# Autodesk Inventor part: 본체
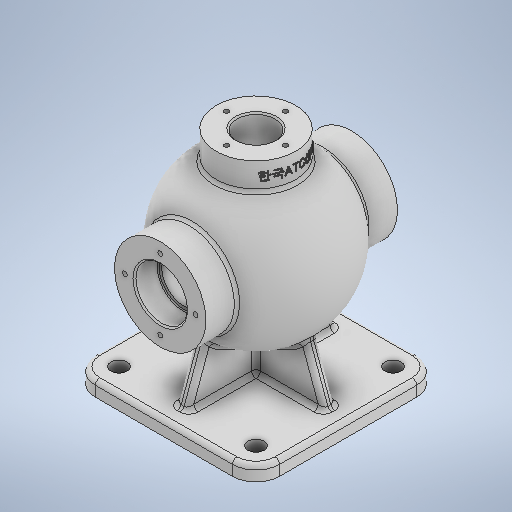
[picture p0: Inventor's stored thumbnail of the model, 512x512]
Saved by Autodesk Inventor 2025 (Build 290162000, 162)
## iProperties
Created: 2024-07
Part Number: 본체
Material: 일반
Document SubType Name: Modeling
Designer: onair
Density: 1 g/cm^3
Appearance: 기본값
Mass: 565.455 g
Surface Area: 1173.81 cm^2
Volume: 565.455 cm^3
Author: onair
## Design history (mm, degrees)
sketch "스케치1"
  geometry: L1 (46.5, -62.5)-(-46.5, -62.5); L2 (-62.5, -46.5)-(-62.5, 46.5); L3 (-46.5, 62.5)-(46.5, 62.5); L4 (62.5, 46.5)-(62.5, -46.5); L5 (62.5, -62.5)-(-62.5, 62.5); L6 (-62.5, -62.5)-(62.5, 62.5); A1 r 16 centre (-46.5, 46.5) between (-46.5, 62.5) and (-62.5, 46.5); A2 r 16 centre (-46.5, -46.5) between (-62.5, -46.5) and (-46.5, -62.5); A3 r 16 centre (46.5, -46.5) between (46.5, -62.5) and (62.5, -46.5); A4 r 16 centre (46.5, 46.5) between (62.5, 46.5) and (46.5, 62.5); 1 further point
  constraints: 12 end point, 8 point on circle, 8 point on line, 8 tangent, 4 centre point, 3 equal radius, 2 midpoint, 2 parallel, 1 horizontal, 1 perpendicular
  dimensions: "d0" = 125 distance of L5.end L6.end; "d1" = 125 distance of L6.start L5.end; "d2" = 16 radius of A1
extrude "돌출1" new body sketch "스케치1" distance "d3" = 10; taper "d4" = 0 deg
sketch "스케치2"
  geometry: A1 r 16 centre (-46.5, -46.5) between (-62.5, -46.5) and (-46.5, -62.5) reference; A2 r 16 centre (-46.5, 46.5) between (-46.5, 62.5) and (-62.5, 46.5) reference; A3 r 16 centre (46.5, 46.5) between (62.5, 46.5) and (46.5, 62.5) reference; A4 r 16 centre (46.5, -46.5) between (46.5, -62.5) and (62.5, -46.5) reference; 5 further points
  constraints: 4 coincident
hole "구멍1" sketch "스케치2" at (-46.5, -46.5), (-46.5, 46.5), (46.5, 46.5), (46.5, -46.5) diameter "d5" = 11; stored, may be unused: countersink angle "d9" = 90 deg, drill point angle "d11" = 120 deg; dims "d6" = 8, "d7" = 4, "d8" = 2, "d10" = 10
sketch "스케치3"
  geometry: L1 (46.5, 10)-(-46.5, 10) reference; L2 (-87.5, 0)-(87.5, 0) reference; L3 (0, -13.909)-(0, 83.453) reference; L4 (-62.5, 0)-(-62.5, 10) reference; L5 (41, 10)-(52, 10) reference; L6 (41, 10)-(52, 10) reference; L7 (-52, 10)-(-41, 10) reference; L8 (-52, 10)-(-41, 10) reference; L9 (-46.5, 10)-(46.5, 10) reference; L10 (46.5, 10)-(62.5, 10) reference; L11 (62.5, 10)-(46.5, 10) reference; L12 (46.5, 10)-(-46.5, 10) reference; L13 (-46.5, 10)-(-62.5, 10) reference; L14 (-62.5, 10)-(-46.5, 10) reference; L15 (-50.5, 10)-(-27.819, 72.316); L16 (50.5, 10)-(27.819, 72.316); L17 (-27.819, 72.316)-(27.819, 72.316); L18 (-50.5, 10)-(50.5, 10); 5 further points; 1 other entity
  constraints: 8 end point, 2 horizontal, 2 symmetric about line, 1 point on line, 1 other
  dimensions: "d15" = 12 distance from line of L4 L15.start; "d16" = 20 deg angle of L15 L4; "d17" = 55.63776 distance of L15.end L16.end
extrude "돌출2" join sketch "스케치3" stored distance "d18" = 8; taper "d19" = 0 deg
sketch "스케치4"
  geometry: L1 (-14.463, 0)-(86.779, 0) reference; L2 (10, -4)-(10, 4) reference; L3 (10, 4)-(10, -4) reference; L4 (10, 52)-(10, 41) reference; L5 (10, -41)-(10, -52) reference; L6 (10, -41)-(10, -52) reference; L7 (10, 52)-(10, 41) reference; L8 (10, 62.5)-(10, 46.5) reference; L9 (10, 46.5)-(10, -46.5) reference; L10 (10, -46.5)-(10, -62.5) reference; L11 (10, -62.5)-(10, -46.5) reference; L12 (10, -46.5)-(10, 46.5) reference; L13 (10, 46.5)-(10, 62.5) reference; L14 (0, 62.5)-(10, 62.5) reference; L15 (0, 62.5)-(10, 62.5) reference; L16 (10, 50.5)-(64.513, 30.659); L17 (10, -50.5)-(64.513, -30.659); L18 (64.513, 30.659)-(64.513, -30.659); 7 further points
  constraints: 6 end point, 2 symmetric about line, 1 point on line, 1 vertical
  dimensions: "d20" = 20 deg angle of L16 L14; "d21" = 12 distance from line of L14 L16.start; "d22" = 61.31806 distance of L16.end L17.end
extrude "돌출3" join sketch "스케치4" stored distance "d23" = 8; taper "d24" = 0 deg
sketch "스케치5"
  geometry: L1 (0, -27.8)-(0, 166.8) reference; L2 (0, 139)-(0, 31); A1 r 54 centre (0, 85) between (0, 31) and (0, 139); 1 further point
  constraints: 3 point on line, 2 end point, 2 point on circle, 1 centre point, 1 collinear
  dimensions: "d25" = 108 diameter of A1; "d26" = 85 distance of point (0, 0) A1.centre
revolve "회전1" sketch "스케치5" stored, may be unused: angle "d27" = 360 deg
sketch "스케치6"
  geometry: C1 r 31 at (0, 85); C2 r 15 at (0, 85); A1 r 54 centre (0, 85) between (37.385, 46.034) and (-37.385, 46.034) reference; 1 further point
  constraints: 2 centre point, 2 coincident
  dimensions: "d28" = 62 diameter of C1; "d29" = 30 diameter of C2
extrude "돌출4" join sketch "스케치6" stored distance "d30" = 130; taper "d31" = 0 deg
extrude "돌출5" cut sketch "스케치6" extent not by distance; stored distance "d32" = 0; taper "d33" = 0 deg
sketch "스케치7" dims "d59" = 48
  geometry: C1 r 31 at (0, 0) reference; C2 r 17.5 at (0, 0); 3 further points
  constraints: 2 coincident, 1 centre point, 1 horizontal alignment, 2 other
  dimensions: "d34" = 35 diameter of C2
sketch "스케치8"
  geometry: C1 r 17.5 at (0, 0) reference; 1 further point
extrude "돌출6" cut sketch "스케치7" distance "d35" = 16; taper "d36" = 0 deg
extrude "돌출7" cut sketch "스케치8" distance "d37" = 16; taper "d38" = 0 deg
node "작업 평면1"
sketch "스케치9" dims "d42" = 40
  geometry: C1 r 27 at (0, 0); C2 r 13 at (0, 0); 3 further points
  constraints: 3 coincident, 2 centre point, 1 vertical alignment, 2 other
  dimensions: "d40" = 54 diameter of C1; "d41" = 26 diameter of C2
extrude "돌출8" join sketch "스케치9" stored distance "d43" = 16; taper "d44" = 0 deg
sketch "스케치10"
  geometry: L1 (102.5, -65)-(67.5, -65) reference; L2 (67.5, 65)-(102.5, 65) reference; L3 (85, 89.341)-(85, -91.884); L4 (-30, 0)-(180, 0) reference; L5 (129, 0)-(41, 0); A1 r 44 centre (85, 0) between (41, 0) and (129, 0); 2 further points
  constraints: 5 point on line, 4 end point, 2 point on circle, 1 centre point, 1 collinear, 1 midpoint, 1 vertical
  dimensions: "d45" = 44 radius of A1
revolve "회전2" sketch "스케치10" stored, may be unused: angle "d46" = 360 deg
extrude "돌출9" cut sketch "스케치9" stored distance "d47" = 10; taper "d48" = 0 deg
hole "구멍2" sketch "스케치9" diameter "d49" = 3.242; stored, may be unused: countersink angle "d53" = 90 deg, drill point angle "d55" = 120 deg; dims "d50" = 9, "d51" = 4, "d52" = 2, "d54" = 11
fillet "모깎기1" dims "d70" = 0.6
chamfer "모따기1" distance "d71" = 1; stored, may be unused: second distance "d72" = 2, angle "d73" = 45 deg
hole "구멍4" sketch "스케치7" diameter "d74" = 3.242; stored, may be unused: countersink angle "d78" = 90 deg, drill point angle "d80" = 120 deg; dims "d75" = 12, "d76" = 4, "d77" = 2, "d79" = 15
fillet "모깎기2" dims "d84" = 3
fillet "모깎기4" dims "d86" = 3
fillet "모깎기5" dims "d87" = 3
fillet "모깎기6" dims "d88" = 3
sketch "스케치11"
  geometry: L1 (150, -27)-(150, 27) reference; L2 (-30, 0)-(180, 0) reference; 2 further points
  constraints: 1 point on line, 1 other
  dimensions: "d89" = 9 distance from line of L1 point (141, 0)
feature "엠보싱1" sketch "스케치11" dims "d0" = 125, "d1" = 125, "d2" = 16, "d90" = 0.5, "d91" = 0
feature "Ѻ耀Ѽ耀Ѿ耀Ҁ耀҂耀҄耀҆耀҈耀" dims "d0" = 125, "d1" = 125, "d2" = 16, "d3" = 10, "d4" = 0, "d5" = 11, "d6" = 8, "d7" = 4, "d8" = 2, "d9" = 90 deg, "d10" = 10, "d11" = 120 deg, "d15" = 12, "d16" = 20 deg, "d17" = 55.63776, "d18" = 8, "d19" = 0, "d20" = 20 deg, "d21" = 12, "d22" = 61.31806, "d23" = 8, "d24" = 0, "d25" = 108, "d26" = 85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
node "솔리드1"
pattern_circular "원형 패턴1" dims angle "d57" = 360 deg
pattern_circular "원형 패턴3" dims angle "d82" = 360 deg
mirror "미러2"
node "투영된 루프1"
node "투영된 루프2"
node "투영된 루프3"
feature "A9D066F2-1C7D-4E18-AEED-F7BC21143FA4" dims "d5" = 11, "d6" = 8, "d7" = 4, "d8" = 2, "d9" = 90 deg, "d10" = 10, "d11" = 120 deg
